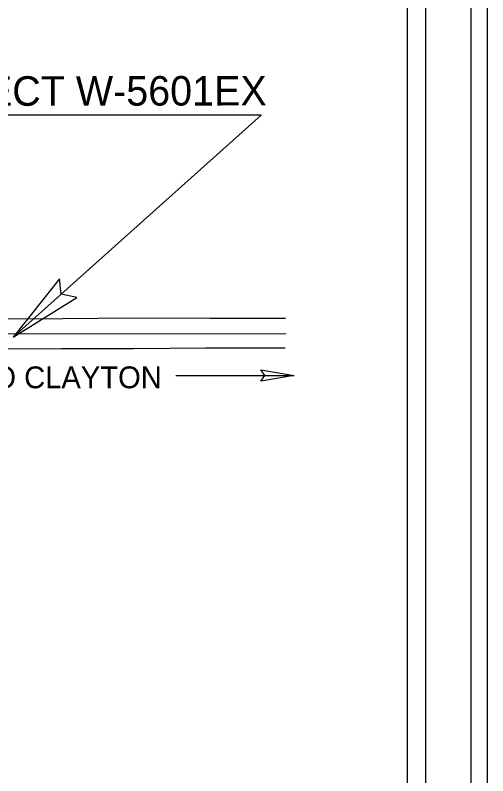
# Model space of a CAD drawing. Extents: x 2105791 to 2114488, y 667759 to 673441.
# Drawn here: x 2113815 to 2114488, y 669912 to 670994 of the extents above; entities that cross this region are included whole.
import ezdxf

# ---------------------------------------------------------------- set-up
doc = ezdxf.new("R2010")
doc.units = 0
for name, color, linetype in [('Exist Roads EOP', 7, 'Continuous'), ('Prop Horizontal Alignment', 7, 'Continuous'), ('Prop PHM Label Text White', 7, 'Continuous'), ('Prop Terminator CELL', 7, 'Continuous'), ('Sheet Plot Border Inside CELL', 7, 'Continuous'), ('Sheet Plot Border Outside CELL', 7, 'Continuous'), ('Sheet Title CELL', 7, 'Continuous'), ('Typical Terminator CELL', 7, 'Continuous')]:
    doc.layers.add(name, color=color, linetype=linetype)

msp = doc.modelspace()

# ---------------------------------------------------------------- linework, layer by layer
at = {"layer": 'Exist Roads EOP'}
for points in [[(2114200, 670562.2), (2114092.7, 670562.3), (2113982.5, 670563), (2113883.1, 670562.1), (2113777.2, 670561.6), (2113691.8, 670561.6), (2113652.6, 670561.4), (2113647.6, 670563.3), (2113645.1, 670564.6), (2113607.9, 670565), (2113604.2, 670563.2), (2113591.2, 670564.1), (2113583.4, 670562.2), (2113488.5, 670561.7), (2113379.9, 670560.8), (2113319.2, 670560.6), (2113216.4, 670560.6), (2113181.6, 670560.9), (2113174.6, 670562.3)], [(2114199.6, 670520.2), (2114086.4, 670520.2), (2113983.7, 670519.3), (2113881.3, 670519.2), (2113778.8, 670519), (2113692.1, 670519.3), (2113609.3, 670518.3), (2113490.8, 670518.5), (2113381.5, 670518.1), (2113321.1, 670517.6), (2113220.2, 670518.1), (2113173.3, 670517.8)]]:
    msp.add_lwpolyline(points, dxfattribs=at)
at = {"layer": 'Prop Horizontal Alignment'}
msp.add_line((2111105.8, 670538.6), (2114200.2, 670541.1), dxfattribs=at)
at = {"layer": 'Prop PHM Label Text White'}
for p, q in [((2114165.1, 670851.3), (2113177.5, 670851.3)), ((2113812.4, 670535.9), (2114165.1, 670851.3)), ((2114043.7, 670481.5), (2114212.1, 670481.5)), ((2114043.7, 670481.5), (2114212.1, 670481.5))]:
    msp.add_line(p, q, dxfattribs=at)
at = {"layer": 'Prop Terminator CELL'}
msp.add_lwpolyline([(2114164.9, 670489.6), (2114212.1, 670481.5), (2114164.6, 670473.1), (2114170.7, 670481.5)], close=True, dxfattribs=at)
msp.add_lwpolyline([(2114164.9, 670489.6), (2114212.1, 670481.5), (2114164.6, 670473.1), (2114170.7, 670481.5)], close=True, dxfattribs=at)
at = {"layer": 'Sheet Plot Border Inside CELL'}
msp.add_lwpolyline([(2105858.2, 667876.6), (2114463.6, 667875.1), (2114464.5, 673323.4), (2105859.1, 673324.8)], close=True, dxfattribs=at)
at = {"layer": 'Sheet Plot Border Outside CELL'}
msp.add_lwpolyline([(2114487.7, 673439.3), (2105792, 673440.8), (2105791, 667760.7), (2114486.8, 667759.2)], close=True, dxfattribs=at)
at = {"layer": 'Sheet Title CELL'}
for points in [[(2114399, 667940), (2114399.9, 673258.6)], [(2114373.4, 668921), (2114374.1, 673232.8)]]:
    msp.add_lwpolyline(points, dxfattribs=at)
at = {"layer": 'Typical Terminator CELL'}
msp.add_lwpolyline([(2113878.3, 670619), (2113812.4, 670535.9), (2113903.1, 670592.1), (2113880.8, 670597)], close=True, dxfattribs=at)

# ---------------------------------------------------------------- texts
at = {"layer": 'Prop PHM Label Text White'}
for s, height, rotation, p in [('END STATE TIP PROJECT W-5601EX', 42, 0.0838, (2113190.2, 670863.9)), ('TO CLAYTON', 31.01, 360, (2113759, 670463.2))]:
    msp.add_text(s, height=height, rotation=rotation, dxfattribs=at).set_placement(p)

doc.saveas('drawing.dxf')
